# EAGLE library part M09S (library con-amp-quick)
AMP QUICK CONNECTOR
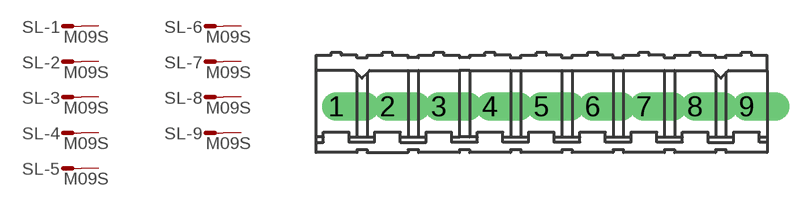
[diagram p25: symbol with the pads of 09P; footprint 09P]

Designator prefix SL; gates -1=M -2=M -3=M -4=M -5=M -6=M -7=M -8=M -9=M

## M09S  [09P]
1  -1:S  pas
2  -2:S  pas
3  -3:S  pas
4  -4:S  pas
5  -5:S  pas
6  -6:S  pas
7  -7:S  pas
8  -8:S  pas
9  -9:S  pas

## Footprint 09P (pad centres in mm)
AMP QUICK CONNECTOR
drill 0.914 offset: 1 -10.16,0; 2 -7.62,0; 3 -5.08,0; 4 -2.54,0; 5 0,0; 6 2.54,0; 7 5.08,0; 8 7.62,0; 9 10.16,0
